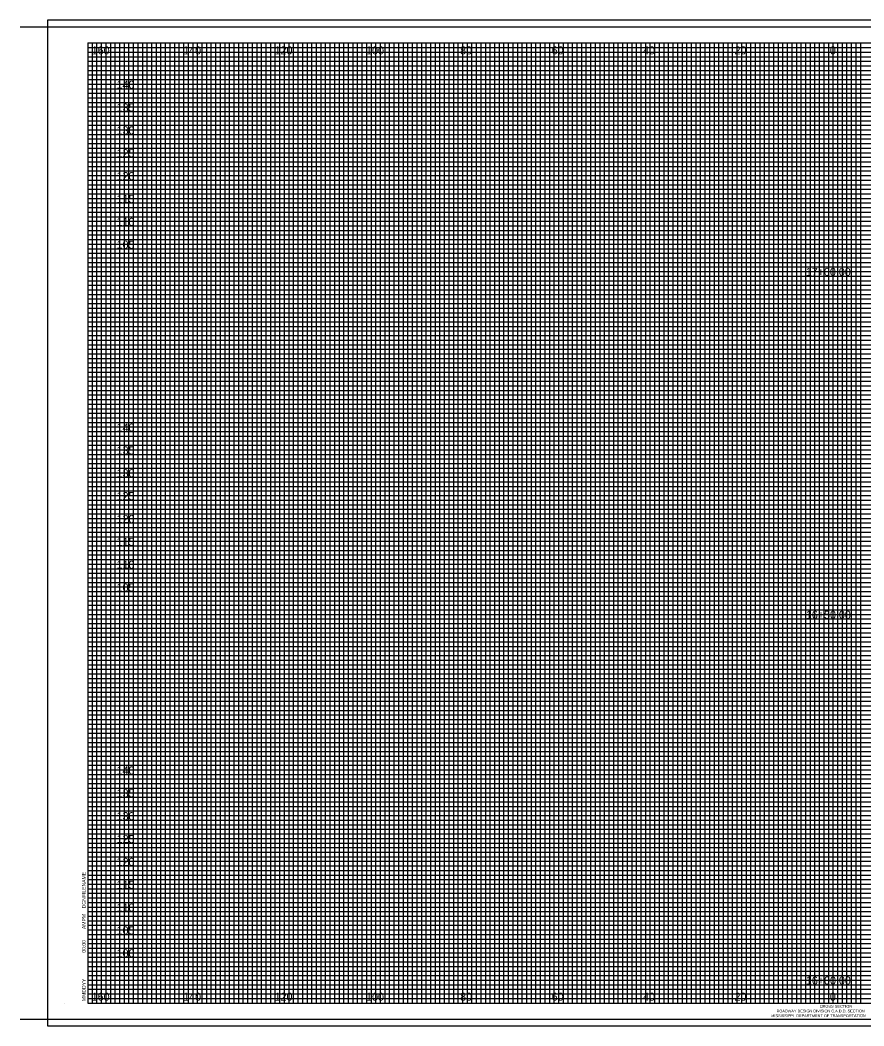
# Model space of a CAD drawing. Extents: x 21281 to 21817, y 6470 to 8300.
# Drawn here: x 21465 to 21649.5, y 7849.8 to 8069.8 of the extents above; entities that cross this region are included whole.
import ezdxf

# ---------------------------------------------------------------- set-up
doc = ezdxf.new("R2010")
doc.units = 0
for name, color, linetype in [('SHEET_BORDER', 7, 'Continuous'), ('SHEET_BORDER_TX', 7, 'Continuous'), ('SHEET_DATE_DGN_TX', 7, 'Continuous'), ('SHEET_PLOTTING_SHAPE', 7, 'Continuous'), ('XS_SHEET_LABELS_ELEVATION', 7, 'Continuous'), ('XS_SHEET_LABELS_OFFSET', 7, 'Continuous'), ('XS_SHEET_LABELS_STATION', 7, 'Continuous'), ('XS_SHEET_MAJOR_GRIDS', 7, 'Continuous'), ('XS_SHEET_MEDIUM_GRIDS', 7, 'Continuous'), ('XS_SHEET_MINOR_GRIDS', 7, 'Continuous')]:
    doc.layers.add(name, color=color, linetype=linetype)

msp = doc.modelspace()

# ---------------------------------------------------------------- linework, layer by layer
at = {"layer": 'SHEET_BORDER'}
for p, q in [((21465.04, 8068.34), (21817.04, 8068.34)), ((21479.84, 8064.84), (21814.84, 8064.84)), ((21479.84, 8064.84), (21479.84, 7854.84)), ((21623.84, 7854.84), (21623.84, 8064.84)), ((21474.84, 7854.84), (21474.84, 7854.84)), ((21479.84, 7854.84), (21814.84, 7854.84)), ((21465.04, 7851.34), (21817.04, 7851.34))]:
    msp.add_line(p, q, dxfattribs=at)
at = {"layer": 'SHEET_PLOTTING_SHAPE'}
msp.add_lwpolyline([(21471.04, 7849.84), (21817.04, 7849.84), (21817.04, 8069.84), (21471.04, 8069.84)], close=True, dxfattribs=at)
at = {"layer": 'XS_SHEET_MAJOR_GRIDS'}
for p, q in [((21484.84, 7854.84), (21484.84, 8064.84)), ((21494.84, 7854.84), (21494.84, 8064.84)), ((21504.84, 7854.84), (21504.84, 8064.84)), ((21514.84, 7854.84), (21514.84, 8064.84)), ((21524.84, 7854.84), (21524.84, 8064.84)), ((21534.84, 7854.84), (21534.84, 8064.84)), ((21544.84, 7854.84), (21544.84, 8064.84)), ((21554.84, 7854.84), (21554.84, 8064.84)), ((21564.84, 7854.84), (21564.84, 8064.84)), ((21574.84, 7854.84), (21574.84, 8064.84)), ((21584.84, 7854.84), (21584.84, 8064.84)), ((21594.84, 7854.84), (21594.84, 8064.84)), ((21604.84, 7854.84), (21604.84, 8064.84)), ((21614.84, 7854.84), (21614.84, 8064.84)), ((21624.84, 7854.84), (21624.84, 8064.84)), ((21634.84, 7854.84), (21634.84, 8064.84)), ((21644.84, 7854.84), (21644.84, 8064.84)), ((21479.84, 8054.84), (21814.84, 8054.84)), ((21479.84, 8044.84), (21814.84, 8044.84)), ((21479.84, 8034.84), (21814.84, 8034.84)), ((21479.84, 8024.84), (21814.84, 8024.84)), ((21479.84, 8014.84), (21814.84, 8014.84)), ((21479.84, 8004.84), (21814.84, 8004.84)), ((21479.84, 7994.84), (21814.84, 7994.84)), ((21479.84, 7984.84), (21814.84, 7984.84)), ((21479.84, 7974.84), (21814.84, 7974.84)), ((21479.84, 7964.84), (21814.84, 7964.84)), ((21479.84, 7954.84), (21814.84, 7954.84)), ((21479.84, 7944.84), (21814.84, 7944.84)), ((21479.84, 7934.84), (21814.84, 7934.84)), ((21479.84, 7924.84), (21814.84, 7924.84)), ((21479.84, 7914.84), (21814.84, 7914.84)), ((21479.84, 7904.84), (21814.84, 7904.84)), ((21479.84, 7894.84), (21814.84, 7894.84)), ((21479.84, 7884.84), (21814.84, 7884.84)), ((21479.84, 7874.84), (21814.84, 7874.84)), ((21479.84, 7864.84), (21814.84, 7864.84))]:
    msp.add_line(p, q, dxfattribs=at)
at = {"layer": 'XS_SHEET_MEDIUM_GRIDS'}
for p, q in [((21489.84, 7854.84), (21489.84, 8064.84)), ((21499.84, 7854.84), (21499.84, 8064.84)), ((21509.84, 7854.84), (21509.84, 8064.84)), ((21519.84, 7854.84), (21519.84, 8064.84)), ((21529.84, 7854.84), (21529.84, 8064.84)), ((21539.84, 7854.84), (21539.84, 8064.84)), ((21549.84, 7854.84), (21549.84, 8064.84)), ((21559.84, 7854.84), (21559.84, 8064.84)), ((21569.84, 7854.84), (21569.84, 8064.84)), ((21579.84, 7854.84), (21579.84, 8064.84)), ((21589.84, 7854.84), (21589.84, 8064.84)), ((21599.84, 7854.84), (21599.84, 8064.84)), ((21609.84, 7854.84), (21609.84, 8064.84)), ((21619.84, 7854.84), (21619.84, 8064.84)), ((21629.84, 7854.84), (21629.84, 8064.84)), ((21639.84, 7854.84), (21639.84, 8064.84)), ((21479.84, 8059.84), (21787.84, 8059.84)), ((21479.84, 8049.84), (21814.84, 8049.84)), ((21479.84, 8039.84), (21814.84, 8039.84)), ((21479.84, 8029.84), (21814.84, 8029.84)), ((21479.84, 8019.84), (21814.84, 8019.84)), ((21479.84, 8009.84), (21814.84, 8009.84)), ((21479.84, 7999.84), (21814.84, 7999.84)), ((21479.84, 7989.84), (21814.84, 7989.84)), ((21479.84, 7979.84), (21814.84, 7979.84)), ((21479.84, 7969.84), (21814.84, 7969.84)), ((21479.84, 7959.84), (21814.84, 7959.84)), ((21479.84, 7949.84), (21814.84, 7949.84)), ((21479.84, 7939.84), (21814.84, 7939.84)), ((21479.84, 7929.84), (21814.84, 7929.84)), ((21479.84, 7919.84), (21814.84, 7919.84)), ((21479.84, 7909.84), (21814.84, 7909.84)), ((21479.84, 7899.84), (21814.84, 7899.84)), ((21479.84, 7889.84), (21814.84, 7889.84)), ((21479.84, 7879.84), (21814.84, 7879.84)), ((21479.84, 7869.84), (21814.84, 7869.84)), ((21479.84, 7859.84), (21804.84, 7859.84))]:
    msp.add_line(p, q, dxfattribs=at)
at = {"layer": 'XS_SHEET_MINOR_GRIDS'}
for p, q in [((21479.84, 8063.84), (21787.84, 8063.84)), ((21480.84, 7854.84), (21480.84, 8064.84)), ((21481.84, 7854.84), (21481.84, 8064.84)), ((21482.84, 7854.84), (21482.84, 8064.84)), ((21483.84, 7854.84), (21483.84, 8064.84)), ((21485.84, 7854.84), (21485.84, 8064.84)), ((21486.84, 7854.84), (21486.84, 8064.84)), ((21487.84, 7854.84), (21487.84, 8064.84)), ((21488.84, 7854.84), (21488.84, 8064.84)), ((21490.84, 7854.84), (21490.84, 8064.84)), ((21491.84, 7854.84), (21491.84, 8064.84)), ((21492.84, 7854.84), (21492.84, 8064.84)), ((21493.84, 7854.84), (21493.84, 8064.84)), ((21495.84, 7854.84), (21495.84, 8064.84)), ((21496.84, 7854.84), (21496.84, 8064.84)), ((21497.84, 7854.84), (21497.84, 8064.84)), ((21498.84, 7854.84), (21498.84, 8064.84)), ((21500.84, 7854.84), (21500.84, 8064.84)), ((21501.84, 7854.84), (21501.84, 8064.84)), ((21502.84, 7854.84), (21502.84, 8064.84)), ((21503.84, 7854.84), (21503.84, 8064.84)), ((21505.84, 7854.84), (21505.84, 8064.84)), ((21506.84, 7854.84), (21506.84, 8064.84)), ((21507.84, 7854.84), (21507.84, 8064.84)), ((21508.84, 7854.84), (21508.84, 8064.84)), ((21510.84, 7854.84), (21510.84, 8064.84)), ((21511.84, 7854.84), (21511.84, 8064.84)), ((21512.84, 7854.84), (21512.84, 8064.84)), ((21513.84, 7854.84), (21513.84, 8064.84)), ((21515.84, 7854.84), (21515.84, 8064.84)), ((21516.84, 7854.84), (21516.84, 8064.84)), ((21517.84, 7854.84), (21517.84, 8064.84)), ((21518.84, 7854.84), (21518.84, 8064.84)), ((21520.84, 7854.84), (21520.84, 8064.84)), ((21521.84, 7854.84), (21521.84, 8064.84)), ((21522.84, 7854.84), (21522.84, 8064.84)), ((21523.84, 7854.84), (21523.84, 8064.84)), ((21525.84, 7854.84), (21525.84, 8064.84)), ((21526.84, 7854.84), (21526.84, 8064.84)), ((21527.84, 7854.84), (21527.84, 8064.84)), ((21528.84, 7854.84), (21528.84, 8064.84)), ((21530.84, 7854.84), (21530.84, 8064.84)), ((21531.84, 7854.84), (21531.84, 8064.84)), ((21532.84, 7854.84), (21532.84, 8064.84)), ((21533.84, 7854.84), (21533.84, 8064.84)), ((21535.84, 7854.84), (21535.84, 8064.84)), ((21536.84, 7854.84), (21536.84, 8064.84)), ((21537.84, 7854.84), (21537.84, 8064.84)), ((21538.84, 7854.84), (21538.84, 8064.84)), ((21540.84, 7854.84), (21540.84, 8064.84)), ((21541.84, 7854.84), (21541.84, 8064.84)), ((21542.84, 7854.84), (21542.84, 8064.84)), ((21543.84, 7854.84), (21543.84, 8064.84)), ((21545.84, 7854.84), (21545.84, 8064.84)), ((21546.84, 7854.84), (21546.84, 8064.84)), ((21547.84, 7854.84), (21547.84, 8064.84)), ((21548.84, 7854.84), (21548.84, 8064.84)), ((21550.84, 7854.84), (21550.84, 8064.84)), ((21551.84, 7854.84), (21551.84, 8064.84)), ((21552.84, 7854.84), (21552.84, 8064.84)), ((21553.84, 7854.84), (21553.84, 8064.84)), ((21555.84, 7854.84), (21555.84, 8064.84)), ((21556.84, 7854.84), (21556.84, 8064.84)), ((21557.84, 7854.84), (21557.84, 8064.84)), ((21558.84, 7854.84), (21558.84, 8064.84)), ((21560.84, 7854.84), (21560.84, 8064.84)), ((21561.84, 7854.84), (21561.84, 8064.84)), ((21562.84, 7854.84), (21562.84, 8064.84)), ((21563.84, 7854.84), (21563.84, 8064.84)), ((21565.84, 7854.84), (21565.84, 8064.84)), ((21566.84, 7854.84), (21566.84, 8064.84)), ((21567.84, 7854.84), (21567.84, 8064.84)), ((21568.84, 7854.84), (21568.84, 8064.84)), ((21570.84, 7854.84), (21570.84, 8064.84)), ((21571.84, 7854.84), (21571.84, 8064.84)), ((21572.84, 7854.84), (21572.84, 8064.84)), ((21573.84, 7854.84), (21573.84, 8064.84)), ((21575.84, 7854.84), (21575.84, 8064.84)), ((21576.84, 7854.84), (21576.84, 8064.84)), ((21577.84, 7854.84), (21577.84, 8064.84)), ((21578.84, 7854.84), (21578.84, 8064.84)), ((21580.84, 7854.84), (21580.84, 8064.84)), ((21581.84, 7854.84), (21581.84, 8064.84)), ((21582.84, 7854.84), (21582.84, 8064.84)), ((21583.84, 7854.84), (21583.84, 8064.84)), ((21585.84, 7854.84), (21585.84, 8064.84)), ((21586.84, 7854.84), (21586.84, 8064.84)), ((21587.84, 7854.84), (21587.84, 8064.84)), ((21588.84, 7854.84), (21588.84, 8064.84)), ((21590.84, 7854.84), (21590.84, 8064.84)), ((21591.84, 7854.84), (21591.84, 8064.84)), ((21592.84, 7854.84), (21592.84, 8064.84)), ((21593.84, 7854.84), (21593.84, 8064.84)), ((21595.84, 7854.84), (21595.84, 8064.84)), ((21596.84, 7854.84), (21596.84, 8064.84)), ((21597.84, 7854.84), (21597.84, 8064.84)), ((21598.84, 7854.84), (21598.84, 8064.84)), ((21600.84, 7854.84), (21600.84, 8064.84)), ((21601.84, 7854.84), (21601.84, 8064.84)), ((21602.84, 7854.84), (21602.84, 8064.84)), ((21603.84, 7854.84), (21603.84, 8064.84)), ((21605.84, 7854.84), (21605.84, 8064.84)), ((21606.84, 7854.84), (21606.84, 8064.84)), ((21607.84, 7854.84), (21607.84, 8064.84)), ((21608.84, 7854.84), (21608.84, 8064.84)), ((21610.84, 7854.84), (21610.84, 8064.84)), ((21611.84, 7854.84), (21611.84, 8064.84)), ((21612.84, 7854.84), (21612.84, 8064.84)), ((21613.84, 7854.84), (21613.84, 8064.84)), ((21615.84, 7854.84), (21615.84, 8064.84)), ((21616.84, 7854.84), (21616.84, 8064.84)), ((21617.84, 7854.84), (21617.84, 8064.84)), ((21618.84, 7854.84), (21618.84, 8064.84)), ((21620.84, 7854.84), (21620.84, 8064.84)), ((21621.84, 7854.84), (21621.84, 8064.84)), ((21622.84, 7854.84), (21622.84, 8064.84)), ((21625.84, 7854.84), (21625.84, 8064.84)), ((21626.84, 7854.84), (21626.84, 8064.84)), ((21627.84, 7854.84), (21627.84, 8064.84)), ((21628.84, 7854.84), (21628.84, 8064.84)), ((21630.84, 7854.84), (21630.84, 8064.84)), ((21631.84, 7854.84), (21631.84, 8064.84)), ((21632.84, 7854.84), (21632.84, 8064.84)), ((21633.84, 7854.84), (21633.84, 8064.84)), ((21635.84, 7854.84), (21635.84, 8064.84)), ((21636.84, 7854.84), (21636.84, 8064.84)), ((21637.84, 7854.84), (21637.84, 8064.84)), ((21638.84, 7854.84), (21638.84, 8064.84)), ((21640.84, 7854.84), (21640.84, 8064.84)), ((21641.84, 7854.84), (21641.84, 8064.84)), ((21642.84, 7854.84), (21642.84, 8064.84)), ((21643.84, 7854.84), (21643.84, 8064.84)), ((21645.84, 7854.84), (21645.84, 8064.84)), ((21646.84, 7854.84), (21646.84, 8064.84)), ((21647.84, 7854.84), (21647.84, 8064.84)), ((21648.84, 7854.84), (21648.84, 8064.84)), ((21479.84, 8062.84), (21787.84, 8062.84)), ((21479.84, 8061.84), (21787.84, 8061.84)), ((21479.84, 8060.84), (21787.84, 8060.84)), ((21479.84, 8058.84), (21787.84, 8058.84)), ((21479.84, 8057.84), (21787.84, 8057.84)), ((21479.84, 8056.84), (21787.84, 8056.84)), ((21479.84, 8055.84), (21814.84, 8055.84)), ((21479.84, 8053.84), (21814.84, 8053.84)), ((21479.84, 8052.84), (21814.84, 8052.84)), ((21479.84, 8051.84), (21814.84, 8051.84)), ((21479.84, 8050.84), (21814.84, 8050.84)), ((21479.84, 8048.84), (21814.84, 8048.84)), ((21479.84, 8047.84), (21814.84, 8047.84)), ((21479.84, 8046.84), (21814.84, 8046.84)), ((21479.84, 8045.84), (21814.84, 8045.84)), ((21479.84, 8043.84), (21814.84, 8043.84)), ((21479.84, 8042.84), (21814.84, 8042.84)), ((21479.84, 8041.84), (21814.84, 8041.84)), ((21479.84, 8040.84), (21814.84, 8040.84)), ((21479.84, 8038.84), (21814.84, 8038.84)), ((21479.84, 8037.84), (21814.84, 8037.84)), ((21479.84, 8036.84), (21814.84, 8036.84)), ((21479.84, 8035.84), (21814.84, 8035.84)), ((21479.84, 8033.84), (21814.84, 8033.84)), ((21479.84, 8032.84), (21814.84, 8032.84)), ((21479.84, 8031.84), (21814.84, 8031.84)), ((21479.84, 8030.84), (21814.84, 8030.84)), ((21479.84, 8028.84), (21814.84, 8028.84)), ((21479.84, 8027.84), (21814.84, 8027.84)), ((21479.84, 8026.84), (21814.84, 8026.84)), ((21479.84, 8025.84), (21814.84, 8025.84)), ((21479.84, 8023.84), (21814.84, 8023.84)), ((21479.84, 8022.84), (21814.84, 8022.84)), ((21479.84, 8021.84), (21814.84, 8021.84)), ((21479.84, 8020.84), (21814.84, 8020.84)), ((21479.84, 8018.84), (21814.84, 8018.84)), ((21479.84, 8017.84), (21814.84, 8017.84)), ((21479.84, 8016.84), (21814.84, 8016.84)), ((21479.84, 8015.84), (21814.84, 8015.84)), ((21479.84, 8013.84), (21814.84, 8013.84)), ((21479.84, 8012.84), (21814.84, 8012.84)), ((21479.84, 8011.84), (21814.84, 8011.84)), ((21479.84, 8010.84), (21814.84, 8010.84)), ((21479.84, 8008.84), (21814.84, 8008.84)), ((21479.84, 8007.84), (21814.84, 8007.84)), ((21479.84, 8006.84), (21814.84, 8006.84)), ((21479.84, 8005.84), (21814.84, 8005.84)), ((21479.84, 8003.84), (21814.84, 8003.84)), ((21479.84, 8002.84), (21814.84, 8002.84)), ((21479.84, 8001.84), (21814.84, 8001.84)), ((21479.84, 8000.84), (21814.84, 8000.84)), ((21479.84, 7998.84), (21814.84, 7998.84)), ((21479.84, 7997.84), (21814.84, 7997.84)), ((21479.84, 7996.84), (21814.84, 7996.84)), ((21479.84, 7995.84), (21814.84, 7995.84)), ((21479.84, 7993.84), (21814.84, 7993.84)), ((21479.84, 7992.84), (21814.84, 7992.84)), ((21479.84, 7991.84), (21814.84, 7991.84)), ((21479.84, 7990.84), (21814.84, 7990.84)), ((21479.84, 7988.84), (21814.84, 7988.84)), ((21479.84, 7987.84), (21814.84, 7987.84)), ((21479.84, 7986.84), (21814.84, 7986.84)), ((21479.84, 7985.84), (21814.84, 7985.84)), ((21479.84, 7983.84), (21814.84, 7983.84)), ((21479.84, 7982.84), (21814.84, 7982.84)), ((21479.84, 7981.84), (21814.84, 7981.84)), ((21479.84, 7980.84), (21814.84, 7980.84)), ((21479.84, 7978.84), (21814.84, 7978.84)), ((21479.84, 7977.84), (21814.84, 7977.84)), ((21479.84, 7976.84), (21814.84, 7976.84)), ((21479.84, 7975.84), (21814.84, 7975.84)), ((21479.84, 7973.84), (21814.84, 7973.84)), ((21479.84, 7972.84), (21814.84, 7972.84)), ((21479.84, 7971.84), (21814.84, 7971.84)), ((21479.84, 7970.84), (21814.84, 7970.84)), ((21479.84, 7968.84), (21814.84, 7968.84)), ((21479.84, 7967.84), (21814.84, 7967.84)), ((21479.84, 7966.84), (21814.84, 7966.84)), ((21479.84, 7965.84), (21814.84, 7965.84)), ((21479.84, 7963.84), (21814.84, 7963.84)), ((21479.84, 7962.84), (21814.84, 7962.84)), ((21479.84, 7961.84), (21814.84, 7961.84)), ((21479.84, 7960.84), (21814.84, 7960.84)), ((21479.84, 7958.84), (21814.84, 7958.84)), ((21479.84, 7957.84), (21814.84, 7957.84)), ((21479.84, 7956.84), (21814.84, 7956.84)), ((21479.84, 7955.84), (21814.84, 7955.84)), ((21479.84, 7953.84), (21814.84, 7953.84)), ((21479.84, 7952.84), (21814.84, 7952.84)), ((21479.84, 7951.84), (21814.84, 7951.84)), ((21479.84, 7950.84), (21814.84, 7950.84)), ((21479.84, 7948.84), (21814.84, 7948.84)), ((21479.84, 7947.84), (21814.84, 7947.84)), ((21479.84, 7946.84), (21814.84, 7946.84)), ((21479.84, 7945.84), (21814.84, 7945.84)), ((21479.84, 7943.84), (21814.84, 7943.84)), ((21479.84, 7942.84), (21814.84, 7942.84)), ((21479.84, 7941.84), (21814.84, 7941.84)), ((21479.84, 7940.84), (21814.84, 7940.84)), ((21479.84, 7938.84), (21814.84, 7938.84)), ((21479.84, 7937.84), (21814.84, 7937.84)), ((21479.84, 7936.84), (21814.84, 7936.84)), ((21479.84, 7935.84), (21814.84, 7935.84)), ((21479.84, 7933.84), (21814.84, 7933.84)), ((21479.84, 7932.84), (21814.84, 7932.84)), ((21479.84, 7931.84), (21814.84, 7931.84)), ((21479.84, 7930.84), (21814.84, 7930.84)), ((21479.84, 7928.84), (21814.84, 7928.84)), ((21479.84, 7927.84), (21814.84, 7927.84)), ((21479.84, 7926.84), (21814.84, 7926.84)), ((21479.84, 7925.84), (21814.84, 7925.84)), ((21479.84, 7923.84), (21814.84, 7923.84)), ((21479.84, 7922.84), (21814.84, 7922.84)), ((21479.84, 7921.84), (21814.84, 7921.84)), ((21479.84, 7920.84), (21814.84, 7920.84)), ((21479.84, 7918.84), (21814.84, 7918.84)), ((21479.84, 7917.84), (21814.84, 7917.84)), ((21479.84, 7916.84), (21814.84, 7916.84)), ((21479.84, 7915.84), (21814.84, 7915.84)), ((21479.84, 7913.84), (21814.84, 7913.84)), ((21479.84, 7912.84), (21814.84, 7912.84)), ((21479.84, 7911.84), (21814.84, 7911.84)), ((21479.84, 7910.84), (21814.84, 7910.84)), ((21479.84, 7908.84), (21814.84, 7908.84)), ((21479.84, 7907.84), (21814.84, 7907.84)), ((21479.84, 7906.84), (21814.84, 7906.84)), ((21479.84, 7905.84), (21814.84, 7905.84)), ((21479.84, 7903.84), (21814.84, 7903.84)), ((21479.84, 7902.84), (21814.84, 7902.84)), ((21479.84, 7901.84), (21814.84, 7901.84)), ((21479.84, 7900.84), (21814.84, 7900.84)), ((21479.84, 7898.84), (21814.84, 7898.84)), ((21479.84, 7897.84), (21814.84, 7897.84)), ((21479.84, 7896.84), (21814.84, 7896.84)), ((21479.84, 7895.84), (21814.84, 7895.84)), ((21479.84, 7893.84), (21814.84, 7893.84)), ((21479.84, 7892.84), (21814.84, 7892.84)), ((21479.84, 7891.84), (21814.84, 7891.84)), ((21479.84, 7890.84), (21814.84, 7890.84)), ((21479.84, 7888.84), (21814.84, 7888.84)), ((21479.84, 7887.84), (21814.84, 7887.84)), ((21479.84, 7886.84), (21814.84, 7886.84)), ((21479.84, 7885.84), (21814.84, 7885.84)), ((21479.84, 7883.84), (21814.84, 7883.84)), ((21479.84, 7882.84), (21814.84, 7882.84)), ((21479.84, 7881.84), (21814.84, 7881.84)), ((21479.84, 7880.84), (21814.84, 7880.84)), ((21479.84, 7878.84), (21814.84, 7878.84)), ((21479.84, 7877.84), (21814.84, 7877.84)), ((21479.84, 7876.84), (21814.84, 7876.84)), ((21479.84, 7875.84), (21814.84, 7875.84)), ((21479.84, 7875.84), (21814.84, 7875.84)), ((21479.84, 7875.84), (21814.84, 7875.84)), ((21479.84, 7873.84), (21814.84, 7873.84)), ((21479.84, 7872.84), (21814.84, 7872.84)), ((21479.84, 7871.84), (21814.84, 7871.84)), ((21479.84, 7870.84), (21814.84, 7870.84)), ((21479.84, 7868.84), (21814.84, 7868.84)), ((21479.84, 7867.84), (21814.84, 7867.84)), ((21479.84, 7866.84), (21814.84, 7866.84)), ((21479.84, 7865.84), (21814.84, 7865.84)), ((21479.84, 7863.84), (21804.84, 7863.84)), ((21479.84, 7862.84), (21804.84, 7862.84)), ((21479.84, 7861.84), (21804.84, 7861.84)), ((21479.84, 7860.84), (21804.84, 7860.84)), ((21479.84, 7860.84), (21804.84, 7860.84)), ((21479.84, 7860.84), (21804.84, 7860.84)), ((21479.84, 7858.84), (21804.84, 7858.84)), ((21479.84, 7857.84), (21804.84, 7857.84)), ((21479.84, 7856.84), (21804.84, 7856.84)), ((21479.84, 7855.84), (21804.84, 7855.84))]:
    msp.add_line(p, q, dxfattribs=at)

# ---------------------------------------------------------------- texts
at = {"layer": 'SHEET_BORDER_TX'}
for s, height, p in [('CROSS SECTION', 0.62, (21639.87, 7853.81)), ('MISSISSIPPI  DEPARTMENT OF TRANSPORTATION', 0.61, (21629.27, 7851.75)), ('ROADWAY DESIGN DIVISION C.A.D.D. SECTION', 0.61, (21630.44, 7852.78))]:
    msp.add_text(s, height=height, dxfattribs=at).set_placement(p)
at = {"layer": 'SHEET_DATE_DGN_TX'}
for s, p in [('DGNFILENAME', (21479.37, 7875.54)), ('AMPM', (21479.37, 7871.02)), ('00:00', (21479.37, 7865.84)), ('MMDDYY', (21479.37, 7855.26))]:
    msp.add_text(s, height=0.8, rotation=90, dxfattribs=at).set_placement(p)
at = {"layer": 'XS_SHEET_LABELS_ELEVATION'}
for s, p in [('  140  ', (21484.84, 8054.84)), ('  135  ', (21484.84, 8049.84)), ('  130  ', (21484.84, 8044.84)), ('  125  ', (21484.84, 8039.84)), ('  120  ', (21484.84, 8034.84)), ('  115  ', (21484.84, 8029.84)), ('  110  ', (21484.84, 8024.84)), ('  105  ', (21484.84, 8019.84)), ('  140  ', (21484.84, 7979.84)), ('  135  ', (21484.84, 7974.84)), ('  130  ', (21484.84, 7969.84)), ('  125  ', (21484.84, 7964.84)), ('  120  ', (21484.84, 7959.84)), ('  115  ', (21484.84, 7954.84)), ('  110  ', (21484.84, 7949.84)), ('  105  ', (21484.84, 7944.84)), ('  140  ', (21484.84, 7904.84)), ('  135  ', (21484.84, 7899.84)), ('  130  ', (21484.84, 7894.84)), ('  125  ', (21484.84, 7889.84)), ('  120  ', (21484.84, 7884.84)), ('  115  ', (21484.84, 7879.84)), ('  110  ', (21484.84, 7874.84)), ('  105  ', (21484.84, 7869.84)), ('  100  ', (21484.84, 7864.84))]:
    msp.add_text(s, height=1.75, dxfattribs=at).set_placement(p)
at = {"layer": 'XS_SHEET_LABELS_OFFSET'}
for s, p in [('  160  ', (21479.4, 8062.34)), ('  140  ', (21499.39, 8062.34)), ('  120  ', (21519.39, 8062.34)), ('  100  ', (21539.39, 8062.34)), ('  80  ', (21559.95, 8062.34)), ('  60  ', (21579.97, 8062.34)), ('  40  ', (21599.95, 8062.34)), ('  20  ', (21619.95, 8062.34)), ('  0  ', (21640.81, 8062.34)), ('  0  ', (21640.81, 8062.34)), ('  160  ', (21479.4, 7855.34)), ('  140  ', (21499.39, 7855.34)), ('  120  ', (21519.39, 7855.34)), ('  100  ', (21539.39, 7855.34)), ('  80  ', (21559.95, 7855.34)), ('  60  ', (21579.97, 7855.34)), ('  40  ', (21599.95, 7855.34)), ('  20  ', (21619.95, 7855.34)), ('  0  ', (21640.81, 7855.34)), ('  0  ', (21640.81, 7855.34))]:
    msp.add_text(s, height=1.75, dxfattribs=at).set_placement(p)
at = {"layer": 'XS_SHEET_LABELS_STATION'}
for s, p in [('  17+00.00  ', (21635.54, 8013.89)), ('  16+50.00  ', (21635.56, 7938.89)), ('  16+00.00  ', (21635.56, 7858.89))]:
    msp.add_text(s, height=1.75, dxfattribs=at).set_placement(p)

doc.saveas('drawing.dxf')
